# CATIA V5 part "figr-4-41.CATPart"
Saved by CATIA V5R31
Part number: Part1
Bounding box of the stored display mesh (mm): x -89.975 to 89.975, y -89.975 to 89.975, z 0 to 190
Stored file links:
  D:\PROJECTS\Project 2021\US EDITION\CATIA V5 6R 2021\Resources\Part Files\c04_catia_v5_6r2020_prt\figr-4-41.CATPart
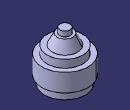
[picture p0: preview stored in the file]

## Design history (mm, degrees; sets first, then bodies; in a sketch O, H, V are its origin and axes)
Set1
  Line1 "Y Axis": stored without definition
  Line2 "Y Axis": stored without definition
  Line3 "X Axis": stored without definition
  Line4 "Z Axis": stored without definition
Body1 (main body)
  Sketch1 on yz-plane, origin (0, 0, 0), H (0, 1, 0), V (0, 0, 1)
    line L1 (0, 0) -> (80, 0)
    line L2 (80, 0) -> (80, 30)
    line L3 (80, 30) -> (90, 30)
    line L4 (90, 30) -> (90, 100)
    line L5 (90, 100) -> (70, 100)
    line L6 (70, 100) -> (70, 130)
    line L7 (70, 130) -> (50, 130)
    line L8 (50, 130) -> (30, 170)
    line L9 (30, 170) -> (20, 170)
    line L10 (20, 170) -> (20, 190)
    line L11 (20, 190) -> (0, 190)
    point P11 (0, 190)
    line L12 (0, 190) -> (0, 0)
    axis line L13 (0, -40) -> (0, 230)
    point P12 (0, -40)
    point P13 (0, 230)
    horizontal: L1 H, L3 H, L5 H, L7 H, L9 H, L11 H
    vertical: L2 V, L4 V, L6 V, L10 V, L12 V, L13 V
    coincidence: P11 V, P12 V, P13 L8
  Shaft1: profile Sketch1, axis Sketch1.L13, angle 360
